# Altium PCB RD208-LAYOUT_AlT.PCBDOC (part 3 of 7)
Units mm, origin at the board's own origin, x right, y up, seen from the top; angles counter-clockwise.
Board outline 240 x 150 mm, 6 copper layers (TOP, Mid-Layer 1, Mid-Layer 2, Mid-Layer 3, Mid-Layer 4, BOTTOM), stack 1.422 mm thick; 773 components, 409 nets, 3936 pads, 97 vias.
Unrouted connection lines stored in the file: 1.
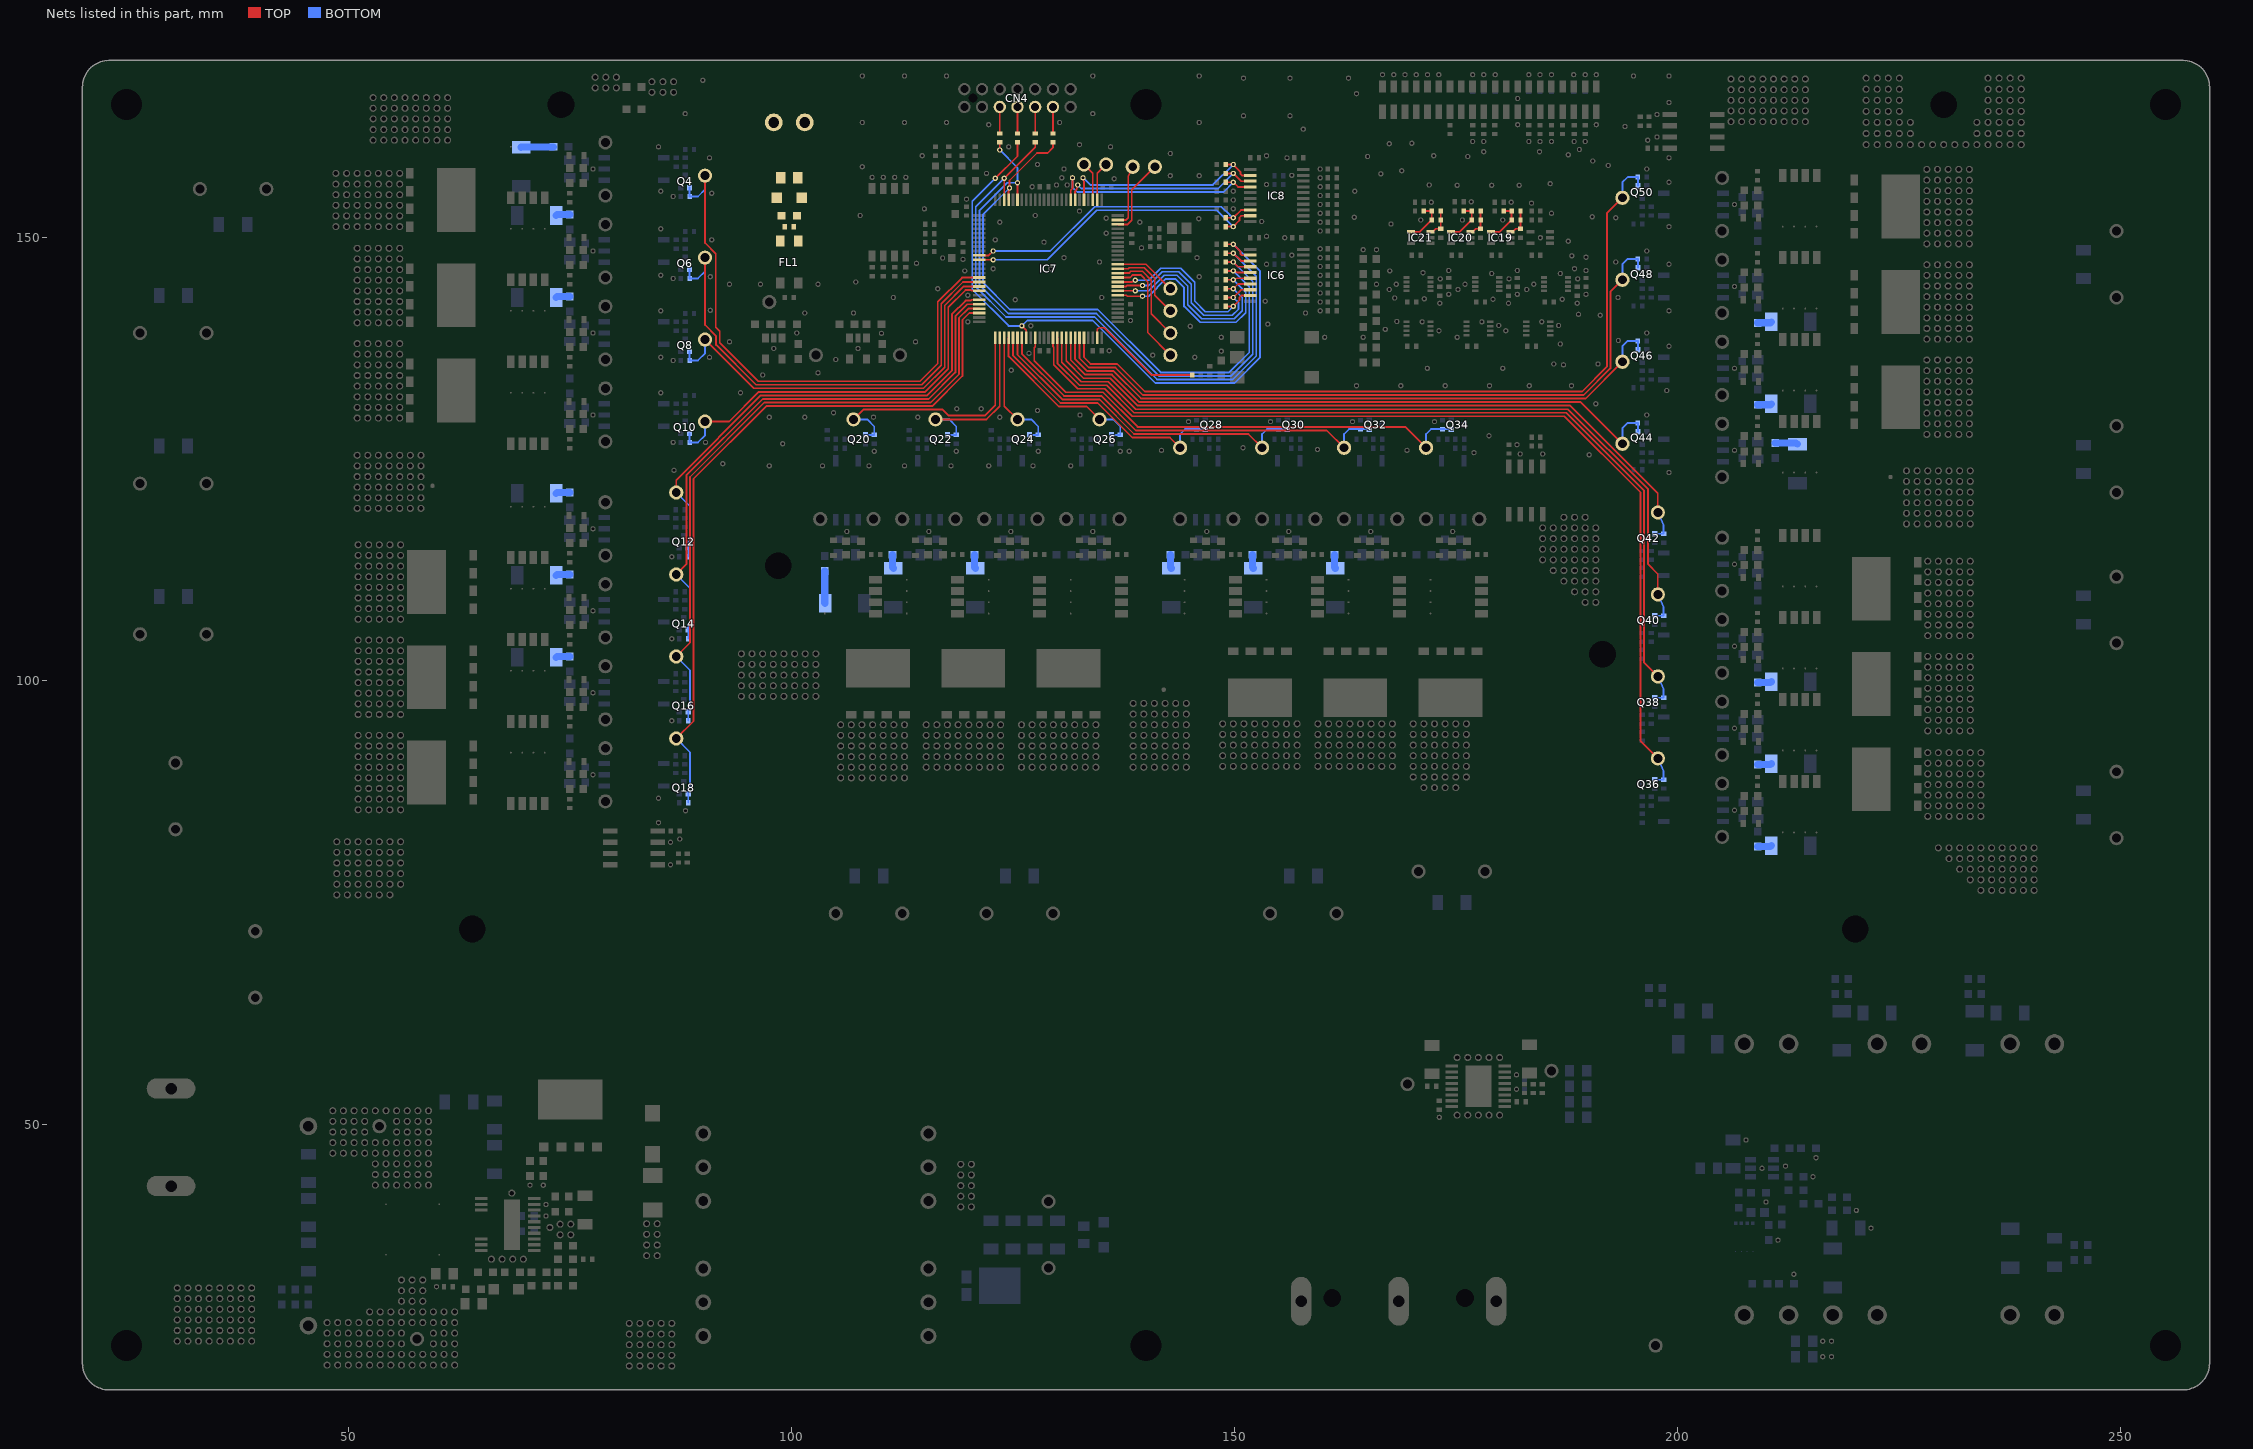
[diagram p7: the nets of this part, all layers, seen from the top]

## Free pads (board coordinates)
  round 0 hole 3.5 unplated paste-3.8 mask+0: ""(25,25) ""(25,165) ""(140,25) ""(140,165) ""(255,25) ""(255,165)
  round 0.8 / inner round 0 / far side round 0.8 hole 0.5 paste-0.8 mask+0: ""(30.7,25.5) ""(30.7,26.7) ""(30.7,27.9) ""(30.7,29.1) ""(30.7,30.3) ""(30.7,31.5) ""(31.9,25.5) ""(31.9,26.7) ""(31.9,27.9) ""(31.9,29.1) ""(31.9,30.3) ""(31.9,31.5) ""(33.1,25.5) ""(33.1,26.7) ""(33.1,27.9) ""(33.1,29.1) ""(33.1,30.3) ""(33.1,31.5) ""(34.3,25.5) ""(34.3,26.7) ""(34.3,27.9) ""(34.3,29.1) ""(34.3,30.3) ""(34.3,31.5) ""(35.5,25.5) ""(35.5,26.7) ""(35.5,27.9) ""(35.5,29.1) ""(35.5,30.3) ""(35.5,31.5) ""(36.7,25.5) ""(36.7,26.7) ""(36.7,27.9) ""(36.7,29.1) ""(36.7,30.3) ""(36.7,31.5) ""(37.9,25.5) ""(37.9,26.7) ""(37.9,27.9) ""(37.9,29.1) ""(37.9,30.3) ""(37.9,31.5) ""(39.1,25.5) ""(39.1,26.7) ""(39.1,27.9) ""(39.1,29.1) ""(39.1,30.3) ""(39.1,31.5) ""(47.6,22.8) ""(47.6,24) ""(47.6,25.2) ""(47.6,26.4) ""(47.6,27.6) ""(48.25,46.7) ""(48.25,47.9) ""(48.25,49.1) ""(48.25,50.3) ""(48.25,51.5) ""(48.6,151.25) ""(48.6,152.45) ""(48.6,153.65) ""(48.6,154.85) ""(48.6,156.05) ""(48.6,157.25) ""(48.7,75.85) ""(48.7,77.05) ""(48.7,78.25) ""(48.7,79.45) ""(48.7,80.65) ""(48.7,81.85) ""(48.8,22.8) ""(48.8,24) ""(48.8,25.2) ""(48.8,26.4) ""(48.8,27.6) ""(49.45,46.7) ""(49.45,47.9) ""(49.45,49.1) ""(49.45,50.3) ""(49.45,51.5) ""(49.8,151.25) ""(49.8,152.45) ""(49.8,153.65) ""(49.8,154.85) ""(49.8,156.05) ""(49.8,157.25) ""(49.9,75.85) ""(49.9,77.05) ""(49.9,78.25) ""(49.9,79.45) ""(49.9,80.65) ""(49.9,81.85) ""(50,22.8) ""(50,24) ""(50,25.2) ""(50,26.4) ""(50,27.6) ""(50.65,46.7) ""(50.65,47.9) ""(50.65,49.1) ""(50.65,50.3) ""(50.65,51.5) ""(51,119.45) ""(51,120.65) ""(51,121.85) ""(51,123.05) ""(51,124.25) ""(51,125.45) ""(51,129.65) ""(51,130.85) ""(51,132.05) ""(51,133.25) ""(51,134.45) ""(51,135.65) ""(51,136.85) ""(51,138.05) ""(51,140.4) ""(51,141.6) ""(51,142.8) ""(51,144) ""(51,145.2) ""(51,146.4) ""(51,147.6) ""(51,148.8) ""(51,151.25) ""(51,152.45) ""(51,153.65) ""(51,154.85) ""(51,156.05) ""(51,157.25) ""(51.1,75.85) ""(51.1,77.05) ""(51.1,78.25) ""(51.1,79.45) ""(51.1,80.65) ""(51.1,81.85) ""(51.1,85.45) ""(51.1,86.65) ""(51.1,87.85) ""(51.1,89.05) ""(51.1,90.25) ""(51.1,91.45) ""(51.1,92.65) ""(51.1,93.85) ""(51.1,96.2) ""(51.1,97.4) ""(51.1,98.6) ""(51.1,99.8) ""(51.1,101) ""(51.1,102.2) ""(51.1,103.4) ""(51.1,104.6) ""(51.1,106.95) ""(51.1,108.15) ""(51.1,109.35) ""(51.1,110.55) ""(51.1,111.75) ""(51.1,112.95) ""(51.1,114.15) ""(51.1,115.35) ""(51.2,22.8) ""(51.2,24) ""(51.2,25.2) ""(51.2,26.4) ""(51.2,27.6) ""(51.85,46.7) ""(51.85,47.9) ""(51.85,49.1) ""(51.85,50.3) ""(51.85,51.5) ""(52.2,119.45) ""(52.2,120.65) ""(52.2,121.85) ""(52.2,123.05) ""(52.2,124.25) ""(52.2,125.45) ""(52.2,129.65) ""(52.2,130.85) ""(52.2,132.05) ""(52.2,133.25) ""(52.2,134.45) ""(52.2,135.65) ""(52.2,136.85) ""(52.2,138.05) ""(52.2,140.4) ""(52.2,141.6) ""(52.2,142.8) ""(52.2,144) ""(52.2,145.2) ""(52.2,146.4) ""(52.2,147.6) ""(52.2,148.8) ""(52.2,151.25) ""(52.2,152.45) ""(52.2,153.65) ""(52.2,154.85) ""(52.2,156.05) ""(52.2,157.25) ""(52.3,75.85) ""(52.3,77.05) ""(52.3,78.25) ""(52.3,79.45) ""(52.3,80.65) ""(52.3,81.85) ""(52.3,85.45) ""(52.3,86.65) ""(52.3,87.85) ""(52.3,89.05) ""(52.3,90.25) ""(52.3,91.45) ""(52.3,92.65) ""(52.3,93.85) ""(52.3,96.2) ""(52.3,97.4) ""(52.3,98.6) ""(52.3,99.8) ""(52.3,101) ""(52.3,102.2) ""(52.3,103.4) ""(52.3,104.6) ""(52.3,106.95) ""(52.3,108.15) ""(52.3,109.35) ""(52.3,110.55) ""(52.3,111.75) ""(52.3,112.95) ""(52.3,114.15) ""(52.3,115.35) ""(52.4,22.8) ""(52.4,24) ""(52.4,25.2) ""(52.4,26.4) ""(52.4,27.6) ""(52.4,28.8) ""(52.8,161) ""(52.8,162.2) ""(52.8,163.4) ""(52.8,164.6) ""(52.8,165.8) ""(53.05,43.1) ""(53.05,44.3) ""(53.05,45.5) ""(53.05,46.7) ""(53.05,47.9) ""(53.05,51.5) ""(53.4,119.45) ""(53.4,120.65) ""(53.4,121.85) ""(53.4,123.05) ""(53.4,124.25) ""(53.4,125.45) ""(53.4,129.65) ""(53.4,130.85) ""(53.4,132.05) ""(53.4,133.25) ""(53.4,134.45) ""(53.4,135.65) ""(53.4,136.85) ""(53.4,138.05) ""(53.4,140.4) ""(53.4,141.6) ""(53.4,142.8) ""(53.4,144) ""(53.4,145.2) ""(53.4,146.4) ""(53.4,147.6) ""(53.4,148.8) ""(53.4,151.25) ""(53.4,152.45) ""(53.4,153.65) ""(53.4,154.85) ""(53.4,156.05) ""(53.4,157.25) ""(53.5,75.85) ""(53.5,77.05) ""(53.5,78.25) ""(53.5,79.45) ""(53.5,80.65) ""(53.5,81.85) ""(53.5,85.45) ""(53.5,86.65) ""(53.5,87.85) ""(53.5,89.05) ""(53.5,90.25) ""(53.5,91.45) ""(53.5,92.65) ""(53.5,93.85) ""(53.5,96.2) ""(53.5,97.4) ""(53.5,98.6) ""(53.5,99.8) ""(53.5,101) ""(53.5,102.2) ""(53.5,103.4) ""(53.5,104.6) ""(53.5,106.95) ""(53.5,108.15) ""(53.5,109.35) ""(53.5,110.55) ""(53.5,111.75) ""(53.5,112.95) ""(53.5,114.15) ""(53.5,115.35) ""(53.6,22.8) ""(53.6,24) ""(53.6,25.2) ""(53.6,26.4) ""(53.6,27.6) ""(53.6,28.8) ""(54,161) ""(54,162.2) ""(54,163.4) ""(54,164.6) ""(54,165.8) ""(54.25,43.1) ""(54.25,44.3) ""(54.25,45.5) ""(54.25,46.7) ""(54.25,47.9) ""(54.25,51.5) ""(54.6,119.45) ""(54.6,120.65) ""(54.6,121.85) ""(54.6,123.05) ""(54.6,124.25) ""(54.6,125.45) ""(54.6,129.65) ""(54.6,130.85) ""(54.6,132.05) ""(54.6,133.25) ""(54.6,134.45) ""(54.6,135.65) ""(54.6,136.85) ""(54.6,138.05) ""(54.6,140.4) ""(54.6,141.6) ""(54.6,142.8) ""(54.6,144) ""(54.6,145.2) ""(54.6,146.4) ""(54.6,147.6) ""(54.6,148.8) ""(54.6,151.25) ""(54.6,152.45) ""(54.6,153.65) ""(54.6,154.85) ""(54.6,156.05) ""(54.6,157.25) ""(54.7,75.85) ""(54.7,77.05) ""(54.7,78.25) ""(54.7,79.45) ""(54.7,80.65) ""(54.7,81.85) ""(54.7,85.45) ""(54.7,86.65) ""(54.7,87.85) ""(54.7,89.05) ""(54.7,90.25) ""(54.7,91.45) ""(54.7,92.65) ""(54.7,93.85) ""(54.7,96.2) ""(54.7,97.4) ""(54.7,98.6) ""(54.7,99.8) ""(54.7,101) ""(54.7,102.2) ""(54.7,103.4) ""(54.7,104.6) ""(54.7,106.95) ""(54.7,108.15) ""(54.7,109.35) ""(54.7,110.55) ""(54.7,111.75) ""(54.7,112.95) ""(54.7,114.15) ""(54.7,115.35) ""(54.8,22.8) ""(54.8,24) ""(54.8,25.2) ""(54.8,26.4) ""(54.8,27.6) ""(54.8,28.8) ""(55.2,161) ""(55.2,162.2) ""(55.2,163.4) ""(55.2,164.6) ""(55.2,165.8) ""(55.45,43.1) ""(55.45,44.3) ""(55.45,45.5) ""(55.45,46.7) ""(55.45,47.9) ""(55.45,49.1) ""(55.45,50.3) ""(55.45,51.5) ""(55.8,119.45) ""(55.8,120.65) ""(55.8,121.85) ""(55.8,123.05) ""(55.8,124.25) ""(55.8,125.45) ""(55.8,129.65) ""(55.8,130.85) ""(55.8,132.05) ""(55.8,133.25) ""(55.8,134.45) ""(55.8,135.65) ""(55.8,136.85) ""(55.8,138.05) ""(55.8,140.4) ""(55.8,141.6) ""(55.8,142.8) ""(55.8,144) ""(55.8,145.2) ""(55.8,146.4) ""(55.8,147.6) ""(55.8,148.8) ""(55.8,151.25) ""(55.8,152.45) ""(55.8,153.65) ""(55.8,154.85) ""(55.8,156.05) ""(55.8,157.25) ""(55.9,77.05) ""(55.9,78.25) ""(55.9,79.45) ""(55.9,80.65) ""(55.9,81.85) ""(55.9,85.45) ""(55.9,86.65) ""(55.9,87.85) ""(55.9,89.05) ""(55.9,90.25) ""(55.9,91.45) ""(55.9,92.65) ""(55.9,93.85) ""(55.9,96.2) ""(55.9,97.4) ""(55.9,98.6) ""(55.9,99.8) ""(55.9,101) ""(55.9,102.2) ""(55.9,103.4) ""(55.9,104.6) ""(55.9,106.95) ""(55.9,108.15) ""(55.9,109.35) ""(55.9,110.55) ""(55.9,111.75) ""(55.9,112.95) ""(55.9,114.15) ""(55.9,115.35) ""(56,22.8) ""(56,24) ""(56,25.2) ""(56,26.4) ""(56,27.6) ""(56,28.8) ""(56,30) ""(56,31.2) ""(56,32.4) ""(56.4,161) ""(56.4,162.2) ""(56.4,163.4) ""(56.4,164.6) ""(56.4,165.8) ""(56.65,43.1) ""(56.65,44.3) ""(56.65,45.5) ""(56.65,46.7) ""(56.65,47.9) ""(56.65,49.1) ""(56.65,50.3) ""(56.65,51.5) ""(57,119.45) ""(57,120.65) ""(57,121.85) ""(57,123.05) ""(57,124.25) ""(57,125.45) ""(57.2,22.8) ""(57.2,24) ""(57.2,27.6) ""(57.2,28.8) ""(57.2,30) ""(57.2,31.2) ""(57.2,32.4) ""(57.6,161) ""(57.6,162.2) ""(57.6,163.4) ""(57.6,164.6) ""(57.6,165.8) ""(57.85,43.1) ""(57.85,44.3) ""(57.85,45.5) ""(57.85,46.7) ""(57.85,47.9) ""(57.85,49.1) ""(57.85,50.3) ""(57.85,51.5) ""(58.2,119.45) ""(58.2,120.65) ""(58.2,121.85) ""(58.2,123.05) ""(58.2,124.25) ""(58.2,125.45) ""(58.4,22.8) ""(58.4,24) ""(58.4,27.6) ""(58.4,28.8) ""(58.4,30) ""(58.4,31.2) ""(58.4,32.4) ""(58.8,161) ""(58.8,162.2) ""(58.8,163.4) ""(58.8,164.6) ""(58.8,165.8) ""(59.05,43.1) ""(59.05,44.3) ""(59.05,45.5) ""(59.05,46.7) ""(59.05,47.9) ""(59.05,49.1) ""(59.05,50.3) ""(59.05,51.5) ""(59.6,22.8) ""(59.6,24) ""(59.6,25.2) ""(59.6,26.4) ""(59.6,27.6) ""(59.6,28.8) ""(60,161) ""(60,162.2) ""(60,163.4) ""(60,164.6) ""(60,165.8) ""(60.8,22.8) ""(60.8,24) ""(60.8,25.2) ""(60.8,26.4) ""(60.8,27.6) ""(60.8,28.8) ""(61.2,161) ""(61.2,162.2) ""(61.2,163.4) ""(61.2,164.6) ""(61.2,165.8) ""(62,22.8) ""(62,24) ""(62,25.2) ""(62,26.4) ""(62,27.6) ""(62,28.8) ""(66.15,34.75) ""(67.35,34.75) ""(68.45,42.2) ""(68.55,34.75) ""(69.75,34.75) ""(72.75,38.325) ""(73.9,37.5) ""(73.9,38.7) ""(75.1,37.5) ""(75.1,38.7) ""(77.85,166.9) ""(77.85,168.1) ""(79.05,166.9) ""(79.05,168.1) ""(80.25,166.9) ""(80.25,168.1) ""(81.7,22.7) ""(81.7,23.9) ""(81.7,25.1) ""(81.7,26.3) ""(81.7,27.5) ""(82.9,22.7) ""(82.9,23.9) ""(82.9,25.1) ""(82.9,26.3) ""(82.9,27.5) ""(83.65,35.15) ""(83.65,36.35) ""(83.65,37.55) ""(83.65,38.75) ""(84.1,22.7) ""(84.1,23.9) ""(84.1,25.1) ""(84.1,26.3) ""(84.1,27.5) ""(84.25,166.4) ""(84.25,167.6) ""(84.85,35.15) ""(84.85,36.35) ""(84.85,37.55) ""(84.85,38.75) ""(85.3,22.7) ""(85.3,23.9) ""(85.3,25.1) ""(85.3,26.3) ""(85.3,27.5) ""(85.5,166.4) ""(85.5,167.6) ""(86.5,22.7) ""(86.5,23.9) ""(86.5,25.1) ""(86.5,26.3) ""(86.5,27.5) ""(86.7,166.4) ""(86.7,167.6) ""(94.35,98.25) ""(94.35,99.45) ""(94.35,100.65) ""(94.35,101.85) ""(94.35,103.05) ""(95.55,98.25) ""(95.55,99.45) ""(95.55,100.65) ""(95.55,101.85) ""(95.55,103.05) ""(96.75,98.25) ""(96.75,99.45) ""(96.75,100.65) ""(96.75,101.85) ""(96.75,103.05) ""(97.95,98.25) ""(97.95,99.45) ""(97.95,100.65) ""(97.95,101.85) ""(97.95,103.05) ""(99.15,98.25) ""(99.15,99.45) ""(99.15,100.65) ""(99.15,101.85) ""(99.15,103.05) ""(100.35,98.25) ""(100.35,99.45) ""(100.35,100.65) ""(100.35,101.85) ""(100.35,103.05) ""(101.55,98.25) ""(101.55,99.45) ""(101.55,100.65) ""(101.55,101.85) ""(101.55,103.05) ""(102.75,98.25) ""(102.75,99.45) ""(102.75,100.65) ""(102.75,101.85) ""(102.75,103.05) ""(105.55,89.05) ""(105.55,90.25) ""(105.55,91.45) ""(105.55,92.65) ""(105.55,93.85) ""(105.55,95.05) ""(106.75,89.05) ""(106.75,90.25) ""(106.75,91.45) ""(106.75,92.65) ""(106.75,93.85) ""(106.75,95.05) ""(107.95,89.05) ""(107.95,90.25) ""(107.95,91.45) ""(107.95,92.65) ""(107.95,93.85) ""(107.95,95.05) ""(109.15,89.05) ""(109.15,90.25) ""(109.15,91.45) ""(109.15,92.65) ""(109.15,93.85) ""(109.15,95.05) ""(110.35,89.05) ""(110.35,90.25) ""(110.35,91.45) ""(110.35,92.65) ""(110.35,93.85) ""(110.35,95.05) ""(111.55,89.05) ""(111.55,90.25) ""(111.55,91.45) ""(111.55,92.65) ""(111.55,93.85) ""(111.55,95.05) ""(112.75,89.05) ""(112.75,90.25) ""(112.75,91.45) ""(112.75,92.65) ""(112.75,93.85) ""(112.75,95.05) ""(115.2,90.25) ""(115.2,91.45) ""(115.2,92.65) ""(115.2,93.85) ""(115.2,95.05) ""(116.4,90.25) ""(116.4,91.45) ""(116.4,92.65) ""(116.4,93.85) ""(116.4,95.05) ""(117.6,90.25) ""(117.6,91.45) ""(117.6,92.65) ""(117.6,93.85) ""(117.6,95.05) ""(118.8,90.25) ""(118.8,91.45) ""(118.8,92.65) ""(118.8,93.85) ""(118.8,95.05) ""(119.1,40.65) ""(119.1,41.85) ""(119.1,43.05) ""(119.1,44.25) ""(119.1,45.45) ""(120,90.25) ""(120,91.45) ""(120,92.65) ""(120,93.85) ""(120,95.05) ""(120.3,40.65) ""(120.3,41.85) ""(120.3,43.05) ""(120.3,44.25) ""(120.3,45.45) ""(121.2,90.25) ""(121.2,91.45) ""(121.2,92.65) ""(121.2,93.85) ""(121.2,95.05) ""(122.4,90.25) ""(122.4,91.45) ""(122.4,92.65) ""(122.4,93.85) ""(122.4,95.05) ""(123.6,90.25) ""(123.6,91.45) ""(123.6,92.65) ""(123.6,93.85) ""(123.6,95.05) ""(125.95,90.25) ""(125.95,91.45) ""(125.95,92.65) ""(125.95,93.85) ""(125.95,95.05) ""(127.15,90.25) ""(127.15,91.45) ""(127.15,92.65) ""(127.15,93.85) ""(127.15,95.05) ""(128.35,90.25) ""(128.35,91.45) ""(128.35,92.65) ""(128.35,93.85) ""(128.35,95.05) ""(129.55,90.25) ""(129.55,91.45) ""(129.55,92.65) ""(129.55,93.85) ""(129.55,95.05) ""(130.75,90.25) ""(130.75,91.45) ""(130.75,92.65) ""(130.75,93.85) ""(130.75,95.05) ""(131.95,90.25) ""(131.95,91.45) ""(131.95,92.65) ""(131.95,93.85) ""(131.95,95.05) ""(133.15,90.25) ""(133.15,91.45) ""(133.15,92.65) ""(133.15,93.85) ""(133.15,95.05) ""(134.35,90.25) ""(134.35,91.45) ""(134.35,92.65) ""(134.35,93.85) ""(134.35,95.05) ""(138.55,90.25) ""(138.55,91.45) ""(138.55,92.65) ""(138.55,93.85) ""(138.55,95.05) ""(138.55,96.25) ""(138.55,97.45) ""(139.75,90.25) ""(139.75,91.45) ""(139.75,92.65) ""(139.75,93.85) ""(139.75,95.05) ""(139.75,96.25) ""(139.75,97.45) ""(140.95,90.25) ""(140.95,91.45) ""(140.95,92.65) ""(140.95,93.85) ""(140.95,95.05) ""(140.95,96.25) ""(140.95,97.45) ""(142.15,90.25) ""(142.15,91.45) ""(142.15,92.65) ""(142.15,93.85) ""(142.15,95.05) ""(142.15,96.25) ""(142.15,97.45) ""(143.35,90.25) ""(143.35,91.45) ""(143.35,92.65) ""(143.35,93.85) ""(143.35,95.05) ""(143.35,96.25) ""(143.35,97.45) ""(144.55,90.25) ""(144.55,91.45) ""(144.55,92.65) ""(144.55,93.85) ""(144.55,95.05) ""(144.55,96.25) ""(144.55,97.45) ""(148.65,90.35) ""(148.65,91.55) ""(148.65,92.75) ""(148.65,93.95) ""(148.65,95.15) ""(149.85,90.35) ""(149.85,91.55) ""(149.85,92.75) ""(149.85,93.95) ""(149.85,95.15) ""(151.05,90.35) ""(151.05,91.55) ""(151.05,92.75) ""(151.05,93.95) ""(151.05,95.15) ""(152.25,90.35) ""(152.25,91.55) ""(152.25,92.75) ""(152.25,93.95) ""(152.25,95.15) ""(153.45,90.35) ""(153.45,91.55) ""(153.45,92.75) ""(153.45,93.95) ""(153.45,95.15) ""(154.65,90.35) ""(154.65,91.55) ""(154.65,92.75) ""(154.65,93.95) ""(154.65,95.15) ""(155.85,90.35) ""(155.85,91.55) ""(155.85,92.75) ""(155.85,93.95) ""(155.85,95.15) ""(157.05,90.35) ""(157.05,91.55) ""(157.05,92.75) ""(157.05,93.95) ""(157.05,95.15) ""(159.4,90.35) ""(159.4,91.55) ""(159.4,92.75) ""(159.4,93.95) ""(159.4,95.15) ""(160.6,90.35) ""(160.6,91.55) ""(160.6,92.75) ""(160.6,93.95) ""(160.6,95.15) ""(161.8,90.35) ""(161.8,91.55) ""(161.8,92.75) ""(161.8,93.95) ""(161.8,95.15) ""(163,90.35) ""(163,91.55) ""(163,92.75) ""(163,93.95) ""(163,95.15) ""(164.2,90.35) ""(164.2,91.55) ""(164.2,92.75) ""(164.2,93.95) ""(164.2,95.15) ""(165.4,90.35) ""(165.4,91.55) ""(165.4,92.75) ""(165.4,93.95) ""(165.4,95.15) ""(166.6,90.35) ""(166.6,91.55) ""(166.6,92.75) ""(166.6,93.95) ""(166.6,95.15) ""(167.8,90.35) ""(167.8,91.55) ""(167.8,92.75) ""(167.8,93.95) ""(167.8,95.15) ""(170.15,89.15) ""(170.15,90.35) ""(170.15,91.55) ""(170.15,92.75) ""(170.15,93.95) ""(170.15,95.15) ""(171.35,87.95) ""(171.35,89.15) ""(171.35,90.35) ""(171.35,91.55) ""(171.35,92.75) ""(171.35,93.95) ""(171.35,95.15) ""(172.55,87.95) ""(172.55,89.15) ""(172.55,90.35) ""(172.55,91.55) ""(172.55,92.75) ""(172.55,93.95) ""(172.55,95.15) ""(173.75,87.95) ""(173.75,89.15) ""(173.75,90.35) ""(173.75,91.55) ""(173.75,92.75) ""(173.75,93.95) ""(173.75,95.15) ""(174.95,87.95) ""(174.95,89.15) ""(174.95,90.35) ""(174.95,91.55) ""(174.95,92.75) ""(174.95,93.95) ""(174.95,95.15) ""(175.1,51) ""(175.1,57.5) ""(176.15,89.15) ""(176.15,90.35) ""(176.15,91.55) ""(176.15,92.75) ""(176.15,93.95) ""(176.15,95.15) ""(176.3,51) ""(176.3,57.5) ""(177.5,51) ""(177.5,57.5) ""(178.7,51) ""(178.7,57.5) ""(179.9,51) ""(179.9,57.5) ""(184.75,113.65) ""(184.75,114.85) ""(184.75,116.05) ""(184.75,117.25) ""(185.95,112.45) ""(185.95,113.65) ""(185.95,114.85) ""(185.95,116.05) ""(185.95,117.25) ""(187.15,111.25) ""(187.15,112.45) ""(187.15,113.65) ""(187.15,114.85) ""(187.15,116.05) ""(187.15,117.25) ""(187.15,118.45) ""(188.35,110.05) ""(188.35,111.25) ""(188.35,112.45) ""(188.35,113.65) ""(188.35,114.85) ""(188.35,116.05) ""(188.35,117.25) ""(188.35,118.45) ""(189.55,108.85) ""(189.55,110.05) ""(189.55,111.25) ""(189.55,112.45) ""(189.55,113.65) ""(189.55,114.85) ""(189.55,116.05) ""(189.55,117.25) ""(189.55,118.45) ""(190.75,108.85) ""(190.75,110.05) ""(190.75,111.25) ""(190.75,112.45) ""(190.75,113.65) ""(190.75,114.85) ""(190.75,116.05) ""(190.75,117.25) ""(206,163.1) ""(206,164.3) ""(206,165.5) ""(206,166.7) ""(206,167.9) ""(207.2,163.1) ""(207.2,164.3) ""(207.2,165.5) ""(207.2,166.7) ""(207.2,167.9) ""(208.4,163.1) ""(208.4,164.3) ""(208.4,165.5) ""(208.4,166.7) ""(208.4,167.9) ""(209.6,163.1) ""(209.6,164.3) ""(209.6,165.5) ""(209.6,166.7) ""(209.6,167.9) ""(210.8,163.1) ""(210.8,164.3) ""(210.8,165.5) ""(210.8,166.7) ""(210.8,167.9) ""(212,163.1) ""(212,164.3) ""(212,165.5) ""(212,166.7) ""(212,167.9) ""(213.2,163.1) ""(213.2,164.3) ""(213.2,165.5) ""(213.2,166.7) ""(213.2,167.9) ""(214.4,163.1) ""(214.4,164.3) ""(214.4,165.5) ""(214.4,166.7) ""(214.4,167.9) ""(221.25,160.5) ""(221.25,161.75) ""(221.25,163) ""(221.25,164.25) ""(221.25,165.5) ""(221.25,166.75) ""(221.25,168) ""(222.5,160.5) ""(222.5,161.75) ""(222.5,163) ""(222.5,164.25) ""(222.5,165.5) ""(222.5,166.75) ""(222.5,168) ""(223.75,160.5) ""(223.75,161.75) ""(223.75,163) ""(223.75,164.25) ""(223.75,165.5) ""(223.75,166.75) ""(223.75,168) ""(225,160.5) ""(225,161.75) ""(225,163) ""(225,164.25) ""(225,165.5) ""(225,166.75) ""(225,168) ""(225.8,117.7) ""(225.8,118.9) ""(225.8,120.1) ""(225.8,121.3) ""(225.8,122.5) ""(225.8,123.7) ""(226.25,160.5) ""(226.25,161.75) ""(226.25,163) ""(227,117.7) ""(227,118.9) ""(227,120.1) ""(227,121.3) ""(227,122.5) ""(227,123.7) ""(227.5,160.5) ""(228.1,127.8) ""(228.1,129) ""(228.1,130.2) ""(228.1,131.4) ""(228.1,132.6) ""(228.1,133.8) ""(228.1,135) ""(228.1,136.2) ""(228.1,138.55) ""(228.1,139.75) ""(228.1,140.95) ""(228.1,142.15) ""(228.1,143.35) ""(228.1,144.55) ""(228.1,145.75) ""(228.1,146.95) ""(228.1,149.3) ""(228.1,150.5) ""(228.1,151.7) ""(228.1,152.9) ""(228.1,154.1) ""(228.1,155.3) ""(228.1,156.5) ""(228.1,157.7) ""(228.2,84.7) ""(228.2,85.9) ""(228.2,87.1) ""(228.2,88.3) ""(228.2,89.5) ""(228.2,90.7) ""(228.2,91.9) ""(228.2,94.35) ""(228.2,95.55) ""(228.2,96.75) ""(228.2,97.95) ""(228.2,99.15) ""(228.2,100.35) ""(228.2,101.55) ""(228.2,102.75) ""(228.2,105.1) ""(228.2,106.3) ""(228.2,107.5) ""(228.2,108.7) ""(228.2,109.9) ""(228.2,111.1) ""(228.2,112.3) ""(228.2,113.5) ""(228.2,117.7) ""(228.2,118.9) ""(228.2,120.1) ""(228.2,121.3) ""(228.2,122.5) ""(228.2,123.7) ""(228.75,160.5) ""(229.3,127.8) ""(229.3,129) ""(229.3,130.2) ""(229.3,131.4) ""(229.3,132.6) ""(229.3,133.8) ""(229.3,135) ""(229.3,136.2) ""(229.3,138.55) ""(229.3,139.75) ""(229.3,140.95) ""(229.3,142.15) ""(229.3,143.35) ""(229.3,144.55) ""(229.3,145.75) ""(229.3,146.95) ""(229.3,149.3) ""(229.3,150.5) ""(229.3,151.7) ""(229.3,152.9) ""(229.3,154.1) ""(229.3,155.3) ""(229.3,156.5) ""(229.3,157.7) ""(229.4,81.15) ""(229.4,84.7) ""(229.4,85.9) ""(229.4,87.1) ""(229.4,88.3) ""(229.4,89.5) ""(229.4,90.7) ""(229.4,91.9) ""(229.4,94.35) ""(229.4,95.55) ""(229.4,96.75) ""(229.4,97.95) ""(229.4,99.15) ""(229.4,100.35) ""(229.4,101.55) ""(229.4,102.75) ""(229.4,105.1) ""(229.4,106.3) ""(229.4,107.5) ""(229.4,108.7) ""(229.4,109.9) ""(229.4,111.1) ""(229.4,112.3) ""(229.4,113.5) ""(229.4,117.7) ""(229.4,118.9) ""(229.4,120.1) ""(229.4,121.3) ""(229.4,122.5) ""(229.4,123.7) ""(230,160.5) ""(230.5,127.8) ""(230.5,129) ""(230.5,130.2) ""(230.5,131.4) ""(230.5,132.6) ""(230.5,133.8) ""(230.5,135) ""(230.5,136.2) ""(230.5,138.55) ""(230.5,139.75) ""(230.5,140.95) ""(230.5,142.15) ""(230.5,143.35) ""(230.5,144.55) ""(230.5,145.75) ""(230.5,146.95) ""(230.5,149.3) ""(230.5,150.5) ""(230.5,151.7) ""(230.5,152.9) ""(230.5,154.1) ""(230.5,155.3) ""(230.5,156.5) ""(230.5,157.7) ""(230.6,79.95) ""(230.6,81.15) ""(230.6,84.7) ""(230.6,85.9) ""(230.6,87.1) ""(230.6,88.3) ""(230.6,89.5) ""(230.6,90.7) ""(230.6,91.9) ""(230.6,94.35) ""(230.6,95.55) ""(230.6,96.75) ""(230.6,97.95) ""(230.6,99.15) ""(230.6,100.35) ""(230.6,101.55) ""(230.6,102.75) ""(230.6,105.1) ""(230.6,106.3) ""(230.6,107.5) ""(230.6,108.7) ""(230.6,109.9) ""(230.6,111.1) ""(230.6,112.3) ""(230.6,113.5) ""(230.6,117.7) ""(230.6,118.9) ""(230.6,120.1) ""(230.6,121.3) ""(230.6,122.5) ""(230.6,123.7) ""(231.25,160.5) ""(231.7,127.8) ""(231.7,129) ""(231.7,130.2) ""(231.7,131.4) ""(231.7,132.6) ""(231.7,133.8) ""(231.7,135) ""(231.7,136.2) ""(231.7,138.55) ""(231.7,139.75) ""(231.7,140.95) ""(231.7,142.15) ""(231.7,143.35) ""(231.7,144.55) ""(231.7,145.75) ""(231.7,146.95) ""(231.7,149.3) ""(231.7,150.5) ""(231.7,151.7) ""(231.7,152.9) ""(231.7,154.1) ""(231.7,155.3) ""(231.7,156.5) ""(231.7,157.7) ""(231.8,78.75) ""(231.8,79.95) ""(231.8,81.15) ""(231.8,84.7) ""(231.8,85.9) ""(231.8,87.1) ""(231.8,88.3) ""(231.8,89.5) ""(231.8,90.7) ""(231.8,91.9) ""(231.8,94.35) ""(231.8,95.55) ""(231.8,96.75) ""(231.8,97.95) ""(231.8,99.15) ""(231.8,100.35) ""(231.8,101.55) ""(231.8,102.75) ""(231.8,105.1) ""(231.8,106.3) ""(231.8,107.5) ""(231.8,108.7) ""(231.8,109.9) ""(231.8,111.1) ""(231.8,112.3) ""(231.8,113.5) ""(231.8,117.7) ""(231.8,118.9) ""(231.8,120.1) ""(231.8,121.3) ""(231.8,122.5) ""(231.8,123.7) ""(232.5,160.5) ""(232.9,127.8) ""(232.9,129) ""(232.9,130.2) ""(232.9,131.4) ""(232.9,132.6) ""(232.9,133.8) ""(232.9,135) ""(232.9,136.2) ""(232.9,138.55) ""(232.9,139.75) ""(232.9,140.95) ""(232.9,142.15) ""(232.9,143.35) ""(232.9,144.55) ""(232.9,145.75) ""(232.9,146.95) ""(232.9,149.3) ""(232.9,150.5) ""(232.9,151.7) ""(232.9,152.9) ""(232.9,154.1) ""(232.9,155.3) ""(232.9,156.5) ""(232.9,157.7) ""(233,77.55) ""(233,78.75) ""(233,79.95) ""(233,81.15) ""(233,84.7) ""(233,85.9) ""(233,87.1) ""(233,88.3) ""(233,89.5) ""(233,90.7) ""(233,91.9) ""(233,94.35) ""(233,95.55) ""(233,96.75) ""(233,97.95) ""(233,99.15) ""(233,100.35) ""(233,101.55) ""(233,102.75) ""(233,105.1) ""(233,106.3) ""(233,107.5) ""(233,108.7) ""(233,109.9) ""(233,111.1) ""(233,112.3) ""(233,113.5) ""(233,117.7) ""(233,118.9) ""(233,120.1) ""(233,121.3) ""(233,122.5) ""(233,123.7) ""(233.75,160.5) ""(233.75,161.75) ""(233.75,163) ""(234.2,76.35) ""(234.2,77.55) ""(234.2,78.75) ""(234.2,79.95) ""(234.2,81.15) ""(234.2,84.7) ""(234.2,85.9) ""(234.2,87.1) ""(234.2,88.3) ""(234.2,89.5) ""(234.2,90.7) ""(234.2,91.9) ""(235,160.5) ""(235,161.75) ""(235,163) ""(235,164.25) ""(235,165.5) ""(235,166.75) ""(235,168) ""(235.4,76.35) ""(235.4,77.55) ""(235.4,78.75) ""(235.4,79.95) ""(235.4,81.15) ""(236.25,160.5) ""(236.25,161.75) ""(236.25,163) ""(236.25,164.25) ""(236.25,165.5) ""(236.25,166.75) ""(236.25,168) ""(236.6,76.35) ""(236.6,77.55) ""(236.6,78.75) ""(236.6,79.95) ""(236.6,81.15) ""(237.5,160.5) ""(237.5,161.75) ""(237.5,163) ""(237.5,164.25) ""(237.5,165.5) ""(237.5,166.75) ""(237.5,168) ""(237.8,76.35) ""(237.8,77.55) ""(237.8,78.75) ""(237.8,79.95) ""(237.8,81.15) ""(238.75,160.5) ""(238.75,161.75) ""(238.75,163) ""(238.75,164.25) ""(238.75,165.5) ""(238.75,166.75) ""(238.75,168) ""(239,76.35) ""(239,77.55) ""(239,78.75) ""(239,79.95) ""(239,81.15) ""(240.2,76.35) ""(240.2,77.55) ""(240.2,78.75) ""(240.2,79.95) ""(240.2,81.15)
  round 0.6 / inner round 0 / far side round 0.6 hole 0.3 paste-0.6 mask+0: ""(59.95,31.65) ""(70.5,43.1) ""(72,43.1) ""(72.3,39.625) ""(72.3,40.925) ""(77.6,89.4) ""(77.6,98.65) ""(77.6,107.9) ""(77.6,117.15) ""(77.6,130) ""(77.6,139.25) ""(77.6,148.5) ""(77.6,157.75) ""(85,84) ""(85,86.75) ""(85,160.25) ""(85.25,132.5) ""(85.25,136.5) ""(85.25,141.75) ""(85.25,145.75) ""(85.25,151) ""(85.25,155.25) ""(86.35,79.245) ""(86.35,81.785) ""(86.5,95.5) ""(86.5,104.75) ""(86.5,114) ""(86.65,126.9) ""(86.65,136.15) ""(86.65,145.4) ""(86.65,154.65) ""(86.75,123.75) ""(87.4,82.15) ""(88,164) ""(88.05,85.35) ""(90,167.75) ""(90.3,126.9) ""(90.75,136.5) ""(90.75,159) ""(90.85,141.8) ""(90.85,145.6) ""(91,149.75) ""(91,155) ""(92.25,124.5) ""(93,138.25) ""(93,144.75) ""(94.25,132.5) ""(96.5,144.75) ""(96.75,134.5) ""(97.5,124.25) ""(97.5,129.75) ""(98,137.5) ""(99,126.75) ""(100.6,139.25) ""(101.5,129.75) ""(101.5,141.5) ""(103,134.75) ""(103,144.75) ""(103.5,124.25) ""(104.75,130.25) ""(105,136.25) ""(106.25,116.85) ""(107,141.5) ""(107.25,145) ""(107.5,137.5) ""(107.75,152.5) ""(108,158) ""(108,163) ""(108,168.25) ""(108.75,124.25) ""(109.095,156.8) ""(109.25,129.75) ""(109.35,125.9) ""(110.15,139.2) ""(110.365,156.8) ""(111.5,143.25) ""(111.635,156.8) ""(112.75,124.25) ""(112.75,163) ""(112.75,168.25) ""(112.905,156.8) ""(114,138.25) ""(114.1,147.1) ""(114.25,129.75) ""(114.75,159.25) ""(115,153.25) ""(115.5,116.85) ""(116.5,144.25) ""(117.05,147.7) ""(117.5,163) ""(117.5,168.25) ""(118,124.25) ""(118.6,125.9) ""(118.65,130.7) ""(119.35,147.55) ""(119.55,146.25) ""(119.75,154.35) ""(119.9,140.5) ""(119.9,143.5) ""(121.4,130.7) ""(122,157.25) ""(122.25,124.25) ""(122.25,162.75) ""(122.75,146.5) ""(122.75,147.5) ""(122.75,148.5) ""(123,149.75) ""(123,156.7) ""(123.5,129.75) ""(123.5,151.75) ""(123.5,159.9) ""(124,156.7) ""(124.5,160.25) ""(124.6,155.6) ""(124.75,116.85) ""(124.8,135.05) ""(125.25,143) ""(125.5,156.2) ""(126,140.05) ""(126.8,136.95) ""(127,140.05) ""(127.15,155.75) ""(127.25,124.25) ""(127.5,152.5) ""(127.75,130.5) ""(127.75,158.25) ""(127.85,125.9) ""(128.5,149.5) ""(129.25,146.5) ""(129.9,155.95) ""(130.25,163) ""(130.5,156.75) ""(130.75,147.75) ""(130.75,157.75) ""(131.1,155.95) ""(131.5,124.25) ""(131.7,156.75) ""(132.3,155.95) ""(132.5,153) ""(132.5,160.5) ""(132.55,130) ""(132.9,156.75) ""(134,116.85) ""(134,164) ""(134,168.25) ""(134.75,147.25) ""(135,143.25) ""(135.5,150.5) ""(135.5,152.2) ""(135.85,137.25) ""(136,160.25) ""(136.4,156.65) ""(137.1,125.9) ""(138.1,125.9) ""(138.25,140.65) ""(138.8,144) ""(138.8,145.2) ""(139.3,151.75) ""(139.5,148.85) ""(139.6,143.4) ""(139.6,144.6) ""(140.75,136.75) ""(141.75,126) ""(142.75,157) ""(142.75,159.5) ""(144.8,129.25) ""(145,140) ""(145.5,136.5) ""(145.75,147.75) ""(145.95,152.15) ""(146,145.6) ""(146,157) ""(146,163) ""(146,168.25) ""(146.85,116.85) ""(148.5,137.2) ""(148.5,138.75) ""(149.85,142.25) ""(149.85,143.25) ""(149.85,144.25) ""(149.85,145.25) ""(149.85,146.25) ""(149.85,147.25) ""(149.85,148.25) ""(149.85,149.25) ""(149.85,151.25) ""(149.85,152.25) ""(149.85,153.25) ""(149.85,154.25) ""(149.85,155.25) ""(149.85,156.25) ""(149.85,157.25) ""(149.85,158.25) ""(150.95,126.3) ""(151,163.75) ""(151,168) ""(153.05,151.825) ""(153.45,142.825) ""(153.6,147) ""(153.6,150.15) ""(153.6,156) ""(153.6,159.25) ""(153.75,140.25) ""(154.05,129.25) ""(155.65,150) ""(155.9,159) ""(156.1,116.85) ""(156.25,163.75) ""(156.25,168) ""(156.45,148.025) ""(156.45,157.025) ""(157.75,162.25) ""(158,141.5) ""(159.35,126.1) ""(159.65,141.75) ""(159.65,142.75) ""(159.65,143.75) ""(159.65,144.75) ""(159.65,145.75) ""(159.65,146.75) ""(159.65,147.75) ""(159.65,148.75) ""(159.65,150.75) ""(159.65,151.75) ""(159.65,152.75) ""(159.65,153.75) ""(159.65,154.75) ""(159.65,155.75) ""(159.65,156.75) ""(159.65,157.75) ""(160.15,138.75) ""(162.85,168) ""(163.3,129.25) ""(163.5,152.3) ""(163.55,155.25) ""(163.75,133.3) ""(163.75,166.25) ""(164.5,138.75) ""(164.5,148.65) ""(165,159.15) ""(165.35,116.85) ""(166,144.75) ""(166,148.65) ""(166.5,157.2) ""(166.685,168.4) ""(167,139.65) ""(167.45,144.15) ""(167.45,160.6) ""(167.5,146.25) ""(167.65,151.55) ""(167.955,168.4) ""(168.05,143.2) ""(168.25,144.75) ""(168.3,140.55) ""(168.75,133.3) ""(168.85,157.55) ""(169.225,168.4) ""(169.45,126) ""(170,160.65) ""(170.495,168.4) ""(171,150) ""(171,152) ""(171.15,140.5) ""(171.25,146.05) ""(171.4,143.1) ""(171.75,135.25) ""(171.765,168.4) ""(171.95,155.95) ""(172.2,154) ""(172.45,159.25) ""(172.55,129.25) ""(173.035,168.4) ""(173.05,139.5) ""(173.1,50.75) ""(173.15,142.6) ""(173.2,145.35) ""(173.75,133.3) ""(174.15,143.6) ""(174.15,146.3) ""(174.6,116.85) ""(175.1,138.75) ""(175.1,155.9) ""(175.2,144.15) ""(175.5,150) ""(175.7,152) ""(176,144.75) ""(176.3,159.15) ""(176.7,154.05) ""(176.85,160.85) ""(176.85,168.4) ""(177,125.75) ""(177.9,140.5) ""(178.1,159.7) ""(178.1,160.85) ""(178.1,168.4) ""(178.7,127.65) ""(178.75,133.3) ""(179,145.95) ""(179,155.9) ""(179.15,143.05) ""(179.4,168.4) ""(179.8,140.1) ""(180,150) ""(180.25,135.25) ""(180.25,152) ""(180.6,139.5) ""(180.9,142.6) ""(180.95,145.35) ""(181.2,154) ""(181.8,53.925) ""(181.8,55.55) ""(181.85,126.65) ""(181.9,143.6) ""(181.9,146.3) ""(181.925,162.75) ""(181.925,165.7) ""(182.1,155.9) ""(182.215,125.6) ""(182.95,144.15) ""(183.2,160.85) ""(183.2,168.4) ""(183.25,133.3) ""(183.5,153.9) ""(183.75,144.75) ""(184.4,159.7) ""(184.45,160.85) ""(184.45,168.4) ""(184.5,150) ""(184.65,140.5) ""(184.755,125.6) ""(185.6,156.1) ""(185.75,152.75) ""(185.75,160.85) ""(185.75,168.4) ""(186,135.75) ""(186.55,140.1) ""(186.75,138) ""(186.75,145.95) ""(186.95,143.05) ""(187.1,135.65) ""(187.65,149.6) ""(187.65,159.35) ""(188,133.3) ""(188.05,147.95) ""(188.25,168.4) ""(188.3,160.85) ""(188.35,146.5) ""(188.65,142.6) ""(188.7,145.35) ""(188.8,141.35) ""(188.9,159.95) ""(189.55,160.85) ""(189.55,168.4) ""(189.65,143.6) ""(189.65,146.3) ""(189.65,147.8) ""(190,125.5) ""(190.35,152.35) ""(190.4,158.65) ""(190.75,131.25) ""(190.815,162.75) ""(190.815,168.4) ""(191,135.75) ""(191.25,141.25) ""(192.15,158.15) ""(193,147.25) ""(193,152.25) ""(193.25,143.25) ""(193.3,138.4) ""(194.05,162.55) ""(195,168.25) ""(196.5,130) ""(196.5,139.25) ""(196.5,148.5) ""(196.5,157.75) ""(196.6,161) ""(197.65,161.365) ""(197.65,163.905) ""(198.75,132.75) ""(199,123.5) ""(199,137.75) ""(199,141.75) ""(199,147) ""(199,151.25) ""(199,156.25) ""(199,159) ""(199,165.25) ""(199,168.25) ""(206.4,85.4) ""(206.4,94.65) ""(206.4,103.9) ""(206.4,113.15) ""(206.4,126) ""(206.4,135.25) ""(206.4,144.5) ""(206.4,153.75) ""(207.7,48.2) ""(209.5,45) ""(209.95,41.2) ""(211.3,36.9) ""(212.15,45.25) ""(213.1,33.05) ""(215.25,44.05) ""(215.6,46.2) ""(216.35,23.75) ""(216.35,25.5) ""(217.35,23.75) ""(217.35,25.5) ""(220.15,40.25) ""(221.8,38.25)
  round 0 hole 3 unplated paste-3.3 mask+0: ""(64,72) ""(74,165) ""(98.5,113) ""(191.5,103) ""(220,72) ""(230,165)
  round 0 hole 2 slot 14.75 at 90 deg unplated paste-14.75 mask+0: ""(161,30.375) ""(176,30.375)

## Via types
v1: diameter 0.7, hole 0.3, TOP to BOTTOM, 92 vias
v2: diameter 0.9, hole 0.5, TOP to BOTTOM, 4 vias
v3: diameter 1.6, hole 1, TOP to BOTTOM, 1 vias

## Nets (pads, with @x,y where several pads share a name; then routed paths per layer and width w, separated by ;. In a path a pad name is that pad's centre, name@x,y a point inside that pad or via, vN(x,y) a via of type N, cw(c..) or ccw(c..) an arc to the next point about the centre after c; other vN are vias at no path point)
5V_IN: C23.1 C24.1 CN2.2 D13.K FL1.2 RV1.2
5V_RTN: C23.2 C24.2 CN2.1 D13.A FL1.1 RV1.1
AMP_IU_NI: C96.2 IC19.3 R136.2 R138.2 | length 3.3
  TOP w0.2: IC19.3@181.1,150.65 181.35,150.65 181.7,151 R138.2@182.25,151 C96.2@182.25,152 R136.2@182.25,153
AMP_IU_OUT: C96.1 IC19.4 R136.1 R137.2 | length 4.8
  TOP w0.2: IC19.4@178.9,150.65 179.9,150.65 C96.1@181.25,152 R136.1@181.25,153 R137.2@180.35,153
AMP_IV_NI: C98.2 IC20.3 R139.2 R141.2 | length 3.3
  TOP w0.2: IC20.3@176.6,150.65 176.85,150.65 177.2,151 R141.2@177.75,151 C98.2@177.75,152 R139.2@177.75,153
AMP_IV_OUT: C98.1 IC20.4 R139.1 R140.2 | length 4.8
  TOP w0.2: IC20.4@174.4,150.65 175.4,150.65 C98.1@176.75,152 R139.1@176.75,153 R140.2@175.85,153
AMP_IW_NI: C100.2 IC21.3 R142.2 R144.2 | length 3.3
  TOP w0.2: IC21.3@172.1,150.65 172.35,150.65 172.7,151 R144.2@173.25,151 C100.2@173.25,152 R142.2@173.25,153
AMP_IW_OUT: C100.1 IC21.4 R142.1 R143.2 | length 4.8
  TOP w0.2: IC21.4@169.9,150.65 170.9,150.65 C100.1@172.25,152 R142.1@172.25,153 R143.2@171.35,153
BS_U1: D14.K R80.2 | length 3.7
  BOTTOM w0.8: D14.K@69.5,160.2 69.55,160.25 R80.2@73.15,160.25
BS_U2: D16.K R82.2 | length 1.6
  BOTTOM w0.8: D16.K@73.45,152.5 73.55,152.6 R82.2@75,152.6
BS_U3: D18.K R84.2 | length 1.6
  BOTTOM w0.8: D18.K@73.45,143.25 73.55,143.35 R84.2@75,143.35
BS_U5: D20.K R88.2 | length 1.6
  BOTTOM w0.8: D20.K@73.45,121.15 73.55,121.25 R88.2@75,121.25
BS_U6: D22.K R90.2 | length 1.6
  BOTTOM w0.8: D22.K@73.45,111.9 73.55,112 R90.2@75,112
BS_U7: D24.K R92.2 | length 1.6
  BOTTOM w0.8: D24.K@73.45,102.65 73.55,102.75 R92.2@75,102.75
BS_V1: D26.K R96.2 | length 3.7
  BOTTOM w0.8: R96.2@103.75,112.4 103.75,108.8 D26.K@103.8,108.75
BS_V2: D28.K R98.2 | length 1.6
  BOTTOM w0.8: R98.2@111.4,114.25 111.4,112.8 D28.K@111.5,112.7
BS_V3: D30.K R101.2 | length 1.6
  BOTTOM w0.8: R101.2@120.65,114.25 120.65,112.8 D30.K@120.75,112.7
BS_V5: D32.K R104.2 | length 1.6
  BOTTOM w0.8: R104.2@142.75,114.25 142.75,112.8 D32.K@142.85,112.7
BS_V6: D34.K R106.2 | length 1.6
  BOTTOM w0.8: R106.2@152,114.25 152,112.8 D34.K@152.1,112.7
BS_V7: D36.K R108.2 | length 1.6
  BOTTOM w0.8: R108.2@161.25,114.25 161.25,112.8 D36.K@161.35,112.7
BS_W1: D38.K R112.2 | length 1.6
  BOTTOM w0.8: R112.2@209,81.3 210.45,81.3 D38.K@210.55,81.4
BS_W2: D40.K R114.2 | length 1.6
  BOTTOM w0.8: R114.2@209,90.55 210.45,90.55 D40.K@210.55,90.65
BS_W3: D42.K R116.2 | length 1.6
  BOTTOM w0.8: R116.2@209,99.8 210.45,99.8 D42.K@210.55,99.9
BS_W5: D44.K R120.2 | length 2.6
  BOTTOM w0.8: R120.2@211,126.85 213.35,126.85 D44.K@213.5,126.7
BS_W6: D46.K R122.2 | length 1.6
  BOTTOM w0.8: R122.2@209,131.15 210.45,131.15 D46.K@210.55,131.25
BS_W7: D48.K R124.2 | length 1.6
  BOTTOM w0.8: R124.2@209,140.4 210.45,140.4 D48.K@210.55,140.5
CN_TCK: CN4.6 R75.1 | length 3
  TOP w0.2: R75.1@127.5,161.75 CN4.6@127.5,164.75
CN_TDI: CN4.10 R78.1 | length 3
  TOP w0.2: R78.1@123.5,161.75 CN4.10@123.5,164.75
CN_TDO: CN4.8 R77.1 | length 3
  TOP w0.2: R77.1@125.5,161.75 CN4.8@125.5,164.75
CN_TMS: CN4.4 R76.1 | length 3
  TOP w0.2: R76.1@129.5,161.75 CN4.4@129.5,164.75
CP_MODE: IC6.6 IC7.7 pad.@139.6,143.4 pad.@149.85,145.25 R52.2 | length 26.1
  TOP w0.2: IC7.7@136.8,143.5 137.8,143.5 137.9,143.4 pad.@139.6,143.4 ; R52.2@149,145.25 pad.@149.85,145.25 150.265,145.425 IC6.6@151.75,145.425
  BOTTOM w0.2: pad.@139.6,143.4 140.3,143.4 142.25,145.35 143.3,145.35 144.3,144.35 144.3,142.25 146.1,140.45 150.15,140.45 151.25,141.55 151.25,143.85 pad.@149.85,145.25
CP_RESET: IC6.7 IC7.8 pad.@138.8,144 pad.@149.85,144.25 R53.2 | length 24.3
  TOP w0.2: IC7.8@136.8,144 pad.@138.8,144 ; R53.2@149,144.25 pad.@149.85,144.25 150.375,144.775 IC6.7@151.75,144.775
  BOTTOM w0.2: pad.@138.8,144 140.3,144 142.05,145.75 143.5,145.75 144.7,144.55 144.7,142.45 146.3,140.85 149.95,140.85 150.85,141.75 150.85,143.25 pad.@149.85,144.25
CP_RSV1: IC6.8 IC7.9 pad.@139.6,144.6 pad.@149.85,143.25 R54.2 | length 22.5
  TOP w0.2: IC7.9@136.8,144.5 137.75,144.5 137.85,144.6 pad.@139.6,144.6 ; R54.2@149,143.25 pad.@149.85,143.25 150.725,144.125 IC6.8@151.75,144.125
  BOTTOM w0.2: pad.@139.6,144.6 140.3,144.6 141.85,146.15 143.7,146.15 145.1,144.75 145.1,142.65 146.5,141.25 149.75,141.25 150.45,141.95 150.45,142.65 pad.@149.85,143.25
CP_RSV2: IC6.9 IC7.10 pad.@138.8,145.2 pad.@149.85,142.25 R55.2 | length 20.6
  TOP w0.2: IC7.10@136.8,145 138.397,145 pad.@138.8,145.2 ; R55.2@149,142.25 pad.@149.85,142.25 150.55,142.95 150.55,143.275 150.75,143.475 IC6.9@151.75,143.475
  BOTTOM w0.2: pad.@138.8,145.2 140.3,145.2 141.65,146.55 143.9,146.55 145.5,144.95 145.5,142.85 146.7,141.65 149.25,141.65 pad.@149.85,142.25
CP_RSV3: IC7.60 IC8.8 pad.@122.75,148.5 pad.@149.85,152.25 R72.2 | length 34.5
  TOP w0.2: IC7.60@121.2,148 122.25,148 pad.@122.75,148.5 ; R72.2@149,152.25 pad.@149.85,152.25 150.725,153.125 IC8.8@151.75,153.125
  BOTTOM w0.2: pad.@122.75,148.5 129.2,148.5 134.2,153.5 148.5,153.5 149.486,152.514 pad.@149.85,152.25
CP_RSV4: IC7.61 IC8.9 pad.@122.75,147.5 pad.@149.85,151.25 R73.2 | length 35.2
  TOP w0.2: IC7.61@121.2,147.5 pad.@122.75,147.5 ; R73.2@149,151.25 pad.@149.85,151.25 150.55,151.95 150.55,152.275 150.75,152.475 IC8.9@151.75,152.475
  BOTTOM w0.2: pad.@122.75,147.5 128.85,147.5 134.45,153.1 148,153.1 pad.@149.85,151.25
CP_SW: IC7.99 R209.2 | length 13.9
  TOP w0.2: IC7.99@134.5,138.7 134.5,139.65 134.7,139.85 135.3,139.85 140.65,134.5 R209.2@145.2,134.5
CP_TCK: IC6.3 IC7.48 pad.@124,156.7 pad.@149.85,148.25 R49.2 R75.2 | length 74.3
  TOP w0.2: IC7.48@124,154.3 pad.@124,156.7 127.5,160.2 R75.2@127.5,160.75 ; R49.2@149,148.25 pad.@149.85,148.25 150.725,147.375 IC6.3@151.75,147.375
  BOTTOM w0.2: pad.@124,156.7 120.8,153.5 120.8,144.45 124.2,141.05 134.2,141.05 141.25,134 149.8,134 152.45,136.65 152.45,145.65 pad.@149.85,148.25
CP_TDI: IC6.4 IC7.45 pad.@123.5,159.9 pad.@125.5,156.2 pad.@149.85,147.25 R50.2 R78.2 | length 71.6
  TOP w0.2: pad.@123.5,159.9 R78.2@123.5,160.75 ; IC7.45@125.5,154.3 pad.@125.5,156.2 ; R50.2@149,147.25 pad.@149.85,147.25 150.375,146.725 IC6.4@151.75,146.725
  BOTTOM w0.2: pad.@123.5,159.9 125.5,157.9 pad.@125.5,156.2 124.35,156.2 121.2,153.05 121.2,144.7 124.45,141.45 134.4,141.45 141.45,134.4 149.6,134.4 152.05,136.85 152.05,145.05 pad.@149.85,147.25
CP_TDO: IC6.2 IC7.83 pad.@123,156.7 pad.@126,140.05 pad.@149.85,149.25 R48.2 R77.2 | length 76.2
  TOP w0.2: pad.@123,156.7 125.5,159.2 R77.2@125.5,160.75 ; pad.@126,140.05 126.5,139.55 IC7.83@126.5,138.7 ; R48.2@149,149.25 pad.@149.85,149.25 150.65,148.45 150.65,148.2 150.825,148.025 IC6.2@151.75,148.025
  BOTTOM w0.2: pad.@123,156.7 120.4,154.1 120.4,144.15 124.5,140.05 pad.@126,140.05 126.6,140.65 134,140.65 141.05,133.6 150,133.6 152.85,136.45 152.85,146.25 pad.@149.85,149.25
CP_TMS: IC6.5 IC7.47 pad.@124.6,155.6 pad.@149.85,146.25 R51.2 R76.2 | length 69
  TOP w0.2: IC7.47@124.5,154.3 124.5,155.161 pad.@124.6,155.6 124.6,156.45 127.7,159.55 128.9,159.55 129.5,160.15 R76.2@129.5,160.75 ; R51.2@149,146.25 pad.@149.85,146.25 150.265,146.075 IC6.5@151.75,146.075
  BOTTOM w0.2: pad.@124.6,155.6 121.6,152.6 121.6,144.95 124.65,141.9 134.55,141.9 141.65,134.8 149.4,134.8 151.65,137.05 151.65,144.45 pad.@149.85,146.25
CP_TP9: IC7.11 TP9.1 | length 13.2
  TOP w0.2: IC7.11@136.8,145.5 138.2,145.5 138.5,145.8 139.4,145.8 140.2,145 140.2,139.3 TP9.1@142.75,136.75
CP_TP10: IC7.12 TP10.1 | length 11.1
  TOP w0.2: IC7.12@136.8,146 138.1,146 138.3,146.2 139.6,146.2 140.6,145.2 140.6,141.4 TP10.1@142.75,139.25
CP_TP11: IC7.13 TP11.1 | length 9.1
  TOP w0.2: IC7.13@136.8,146.5 138,146.5 138.1,146.6 139.8,146.6 141,145.4 141,143.5 TP11.1@142.75,141.75
CP_TP12: IC7.14 TP12.1 | length 7.1
  TOP w0.2: IC7.14@136.8,147 140,147 TP12.1@142.75,144.25
CP_TP13: IC7.23 TP13.1 | length 8.9
  TOP w0.2: IC7.23@136.8,151.5 137.95,151.5 138.4,151.95 138.4,155.4 TP13.1@141,158
CP_TP14: IC7.24 TP14.1 | length 7.2
  TOP w0.2: IC7.24@136.8,152 137.75,152 138,152.25 138,156.909 TP14.1@138.5,158
CP_TP15: IC7.27 TP15.1 | length 4.4
  TOP w0.2: IC7.27@134.5,154.3 134.5,157.25 TP15.1@135.5,158.25
CP_TP16: IC7.28 TP16.1 | length 4.4
  TOP w0.2: TP16.1@133,158.25 134,157.25 IC7.28@134,154.3
CP_UH: IC7.30 IC8.2 pad.@132.9,156.75 pad.@149.85,158.25 R66.2 | length 24.1
  TOP w0.2: pad.@132.9,156.75 133,156.311 IC7.30@133,154.3 ; R66.2@149,158.25 pad.@149.85,158.25 150.65,157.45 150.65,157.2 150.825,157.025 IC8.2@151.75,157.025
  BOTTOM w0.2: pad.@132.9,156.75 133.7,155.95 147.55,155.95 pad.@149.85,158.25
CP_UL: IC7.32 IC8.3 pad.@132.3,155.95 pad.@149.85,157.25 R67.2 | length 23.3
  TOP w0.2: IC7.32@132,154.3 132,155.25 132.15,155.4 pad.@132.3,155.95 ; R67.2@149,157.25 pad.@149.85,157.25 150.725,156.375 IC8.3@151.75,156.375
  BOTTOM w0.2: pad.@132.3,155.95 132.7,155.55 148.15,155.55 pad.@149.85,157.25
CP_VGS_U1: IC7.65 Q4.1 R313.1 TP17.1 | length 64.2
  TOP w0.2: TP17.1@90.25,157 90.25,149.4 91.45,148.2 91.45,139.9 91.9,139.45 91.9,138.15 96.25,133.8 114.5,133.8 116.5,135.8 116.5,142.75 119.25,145.5 IC7.65@121.2,145.5
  BOTTOM w0.2: Q4.1@88.5,155.65 R313.1@88.5,154.65 89.45,154.65 90.25,155.45 TP17.1@90.25,157
CP_VGS_U2: IC7.66 Q6.1 R314.1 TP18.1 | length 55.4
  TOP w0.2: TP18.1@90.25,147.75 90.25,140.15 91.5,138.9 91.5,137.9 96,133.4 114.7,133.4 116.9,135.6 116.9,142.55 119.35,145 IC7.66@121.2,145
  BOTTOM w0.2: Q6.1@88.5,146.4 R314.1@88.5,145.4 89.45,145.4 90.25,146.2 TP18.1@90.25,147.75
CP_VGS_U3: IC7.67 Q8.1 R315.1 TP19.1 | length 46.7
  TOP w0.2: TP19.1@90.25,138.5 95.75,133 114.9,133 117.3,135.4 117.3,142.35 119.45,144.5 IC7.67@121.2,144.5
  BOTTOM w0.2: Q8.1@88.5,137.15 R315.1@88.5,136.15 89.45,136.15 90.25,136.95 TP19.1@90.25,138.5
CP_VGS_U4: IC7.68 Q10.1 R316.1 TP20.1 | length 45.8
  TOP w0.2: TP20.1@90.25,129.25 92.95,129.25 96.3,132.6 115.1,132.6 117.7,135.2 117.7,142.15 119.65,144.1 120.25,144.1 120.35,144 IC7.68@121.2,144
  BOTTOM w0.2: Q10.1@88.5,127.9 R316.1@88.5,126.9 89.45,126.9 90.25,127.7 TP20.1@90.25,129.25
CP_VGS_U5: IC7.70 Q12.1 R317.1 TP21.1 | length 55.7
  TOP w0.2: TP21.1@87,121.25 87,122.65 96.55,132.2 115.3,132.2 118.1,135 118.1,141.35 119.65,142.9 120.25,142.9 120.35,143 IC7.70@121.2,143
  BOTTOM w0.2: TP21.1@87,121.25 88.55,119.7 88.55,115.85 88.35,115.65 Q12.1@88.35,115 R317.1@88.35,114
CP_VGS_U6: IC7.71 Q14.1 R318.1 TP22.1 | length 64.4
  TOP w0.2: TP22.1@87,112 88.15,113.15 88.15,123.2 96.75,131.8 115.5,131.8 118.5,134.8 118.5,141.15 119.85,142.5 IC7.71@121.2,142.5
  BOTTOM w0.2: TP22.1@87,112 88.55,110.45 88.55,106.6 88.35,106.4 Q14.1@88.35,105.75 R318.1@88.35,104.75
CP_VGS_U7: IC7.72 Q16.1 R319.1 TP23.1 | length 73.1
  TOP w0.2: TP23.1@87,102.75 88.55,104.3 88.55,123 96.95,131.4 115.7,131.4 118.9,134.6 118.9,140.95 119.95,142 IC7.72@121.2,142
  BOTTOM w0.2: TP23.1@87,102.75 88.55,101.2 88.55,97.35 88.35,97.15 Q16.1@88.35,96.5 R319.1@88.35,95.5
CP_VGS_U8: IC7.73 Q18.1 R320.1 TP24.1 | length 81.8
  TOP w0.2: TP24.1@87,93.5 88.95,95.45 88.95,122.8 97.15,131 115.9,131 119.3,134.4 119.3,140.75 120.05,141.5 IC7.73@121.2,141.5
  BOTTOM w0.2: TP24.1@87,93.5 88.55,91.95 88.55,88.1 88.35,87.9 Q18.1@88.35,87.25 R320.1@88.35,86.25
CP_VGS_V1: IC7.76 Q20.1 R321.1 TP33.1 | length 29.4
  TOP w0.2: TP33.1@107,129.5 108.1,130.6 117.05,130.6 117.7,129.95 121.85,129.95 123,131.1 IC7.76@123,138.7
  BOTTOM w0.2: TP33.1@107,129.5 108.55,129.5 109.35,128.7 R321.1@109.35,127.75 Q20.1@108.35,127.75
CP_VGS_V2: IC7.77 Q22.1 R322.1 TP34.1 | length 20.2
  TOP w0.2: TP34.1@116.25,129.5 122,129.5 123.5,131 IC7.77@123.5,138.7
  BOTTOM w0.2: TP34.1@116.25,129.5 117.8,129.5 118.6,128.7 R322.1@118.6,127.75 Q22.1@117.6,127.75
CP_VGS_V3: IC7.78 Q24.1 R323.1 TP35.1 | length 14.5
  TOP w0.2: IC7.78@124,138.7 124,131 TP35.1@125.5,129.5
  BOTTOM w0.2: TP35.1@125.5,129.5 127.05,129.5 127.85,128.7 R323.1@127.85,127.75 Q24.1@126.85,127.75
CP_VGS_V4: IC7.79 Q26.1 R324.1 TP36.1 | length 19.9
  TOP w0.2: IC7.79@124.5,138.7 124.5,136.6 130.15,130.95 133.3,130.95 TP36.1@134.75,129.5
  BOTTOM w0.2: TP36.1@134.75,129.5 136.3,129.5 137.1,128.7 R324.1@137.1,127.75 Q26.1@136.1,127.75
CP_VGS_V5: IC7.80 Q28.1 R325.1 TP37.1 | length 29.8
  TOP w0.2: IC7.80@125,138.7 125,136.7 130.35,131.35 134.55,131.35 138.45,127.45 142.7,127.45 TP37.1@143.85,126.3
  BOTTOM w0.2: TP37.1@143.85,126.3 143.85,127.85 144.4,128.4 R325.1@145.7,128.4 Q28.1@146.7,128.4
CP_VGS_V6: IC7.81 Q30.1 R326.1 TP38.1 | length 38.5
  TOP w0.2: IC7.81@125.5,138.7 125.5,136.8 130.55,131.75 134.75,131.75 138.65,127.85 151.55,127.85 TP38.1@153.1,126.3
  BOTTOM w0.2: TP38.1@153.1,126.3 153.1,127.85 153.65,128.4 R326.1@154.95,128.4 Q30.1@155.95,128.4
CP_VGS_V7: IC7.82 Q32.1 R327.1 TP39.1 | length 47.2
  TOP w0.2: IC7.82@126,138.7 126,136.9 130.75,132.15 134.95,132.15 138.85,128.25 160.4,128.25 TP39.1@162.35,126.3
  BOTTOM w0.2: TP39.1@162.35,126.3 162.35,127.85 162.9,128.4 R327.1@164.2,128.4 Q32.1@165.2,128.4
CP_VGS_V8: IC7.85 Q34.1 R328.1 TP40.1 | length 55.5
  TOP w0.2: IC7.85@127.5,138.7 127.5,137.7 127.4,137.6 127.4,136.1 130.95,132.55 135.15,132.55 139.05,128.65 169.25,128.65 TP40.1@171.6,126.3
  BOTTOM w0.2: TP40.1@171.6,126.3 171.6,127.85 172.15,128.4 R328.1@173.45,128.4 Q34.1@174.45,128.4
CP_VGS_W1: IC7.89 Q36.1 R329.1 TP49.1 | length 109.6
  TOP w0.2: IC7.89@129.5,138.7 129.5,137.75 129.6,137.65 129.6,135.65 132.3,132.95 135.35,132.95 138.45,129.85 187.2,129.85 195.8,121.25 195.8,93.2 TP49.1@197.75,91.25
  BOTTOM w0.2: Q36.1@197.4,88.85 R329.1@198.4,88.85 198.4,89.8 198.241,90.155 TP49.1@197.75,91.25
CP_VGS_W2: IC7.90 Q38.1 R330.1 TP50.1 | length 100.1
  TOP w0.2: IC7.90@130,138.7 130,135.85 132.5,133.35 135.55,133.35 138.65,130.25 187.4,130.25 196.2,121.45 196.2,102.05 TP50.1@197.75,100.5
  BOTTOM w0.2: Q38.1@197.4,98.1 R330.1@198.4,98.1 198.4,99.05 198.241,99.405 TP50.1@197.75,100.5
CP_VGS_W3: IC7.91 Q40.1 R331.1 TP51.1 | length 90.7
  TOP w0.2: IC7.91@130.5,138.7 130.5,135.95 132.7,133.75 135.75,133.75 138.85,130.65 187.6,130.65 196.65,121.6 196.65,113.15 197.75,112.05 TP51.1@197.75,109.75
  BOTTOM w0.2: Q40.1@197.4,107.35 R331.1@198.4,107.35 198.4,108.3 198.241,108.655 TP51.1@197.75,109.75
CP_VGS_W4: IC7.92 Q42.1 R332.1 TP52.1 | length 81.2
  TOP w0.2: IC7.92@131,138.7 131,136.1 132.95,134.15 135.95,134.15 139.05,131.05 187.85,131.05 197.75,121.15 TP52.1@197.75,119
  BOTTOM w0.2: Q42.1@197.4,116.6 R332.1@198.4,116.6 198.4,117.55 198.241,117.905 TP52.1@197.75,119
CP_VGS_W5: IC7.93 Q44.1 R333.1 TP53.1 | length 73.4
  TOP w0.2: IC7.93@131.5,138.7 131.5,136.2 133.15,134.55 136.15,134.55 139.25,131.45 189.05,131.45 TP53.1@193.75,126.75
  BOTTOM w0.2: TP53.1@193.75,126.75 193.75,128.5 194.35,129.1 R333.1@195.5,129.1 Q44.1@195.5,128.1
CP_VGS_W6: IC7.94 Q46.1 R334.1 TP54.1 | length 72.5
  TOP w0.2: IC7.94@132,138.7 132,136.3 133.35,134.95 136.35,134.95 139.45,131.85 189.6,131.85 TP54.1@193.75,136
  BOTTOM w0.2: TP54.1@193.75,136 193.75,137.75 194.35,138.35 R334.1@195.5,138.35 Q46.1@195.5,137.35
CP_VGS_W7: IC7.95 Q48.1 R335.1 TP55.1 | length 80.5
  TOP w0.2: IC7.95@132.5,138.7 132.5,136.4 133.55,135.35 136.55,135.35 139.65,132.25 189.4,132.25 192.4,135.25 192.4,143.9 TP55.1@193.75,145.25
  BOTTOM w0.2: TP55.1@193.75,145.25 193.75,147 194.35,147.6 R335.1@195.5,147.6 Q48.1@195.5,146.6
CP_VGS_W8: IC7.96 Q50.1 R336.1 TP56.1 | length 88.5
  TOP w0.2: IC7.96@133,138.7 133,136.5 133.75,135.75 136.75,135.75 139.85,132.65 189.2,132.65 192,135.45 192,152.75 TP56.1@193.75,154.5
  BOTTOM w0.2: TP56.1@193.75,154.5 193.75,156.25 194.35,156.85 R336.1@195.5,156.85 Q50.1@195.5,155.85
CP_VH: IC7.33 IC8.4 pad.@131.7,156.75 pad.@149.85,156.25 R68.2 | length 25.4
  TOP w0.2: IC7.33@131.5,154.3 131.5,155.35 131.7,155.55 pad.@131.7,156.75 ; R68.2@149,156.25 pad.@149.85,156.25 150.375,155.725 IC8.4@151.75,155.725
  BOTTOM w0.2: pad.@131.7,156.75 131.7,155.7 132.25,155.15 148.75,155.15 pad.@149.85,156.25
